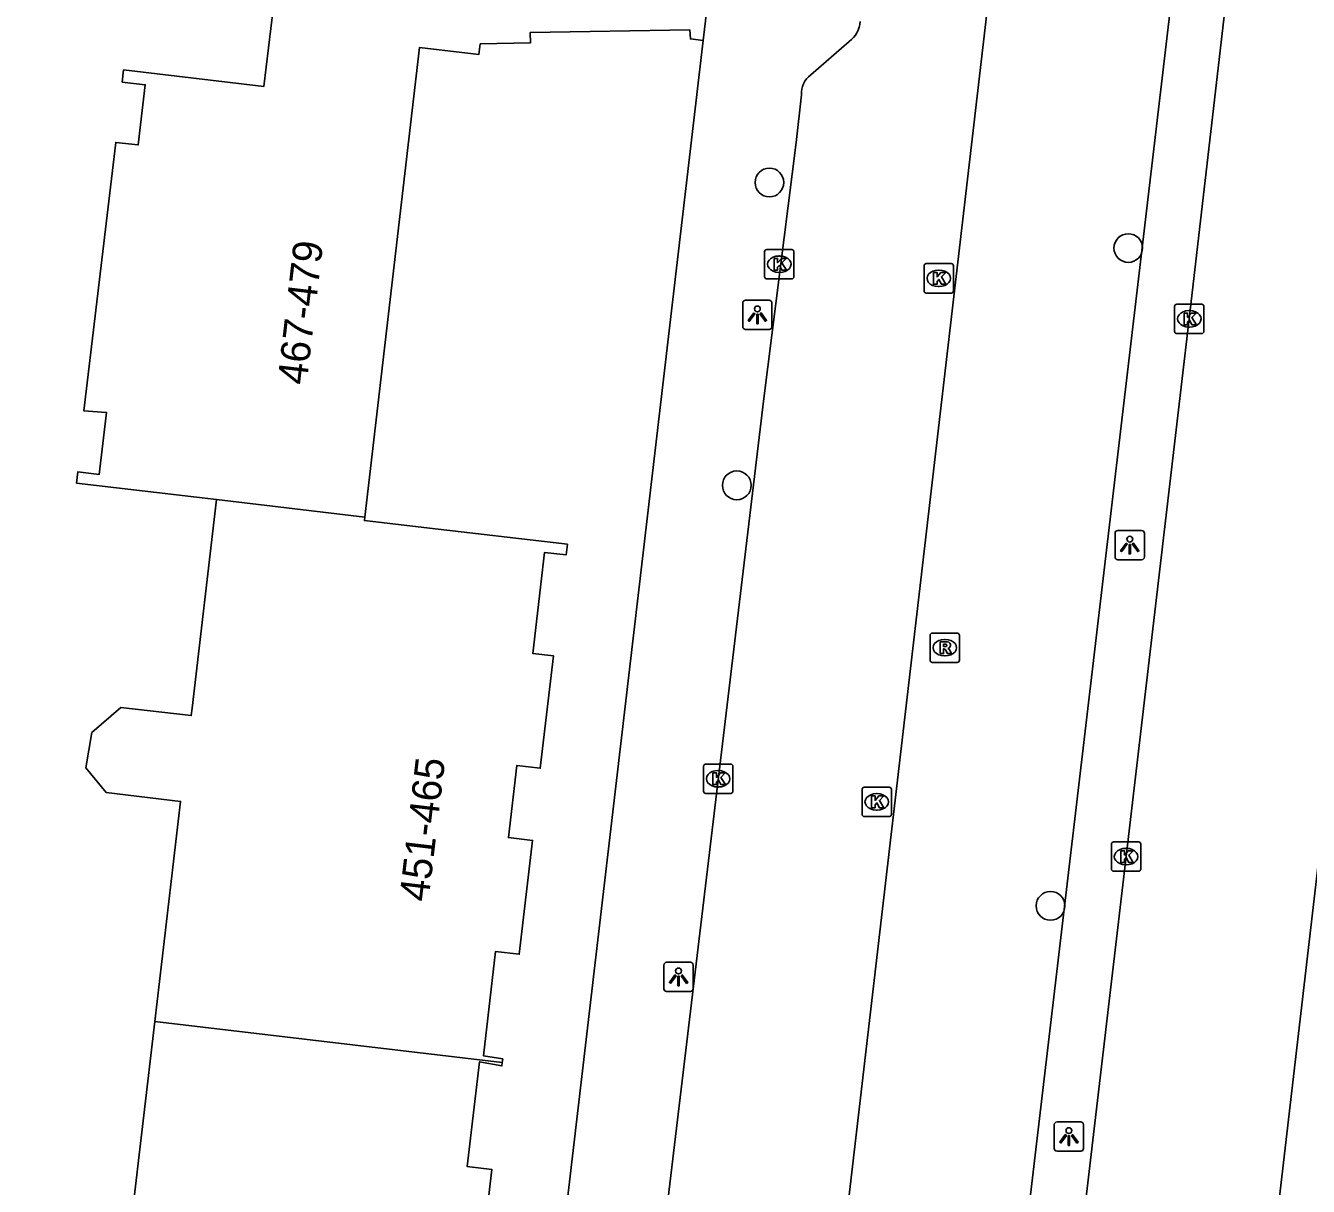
# Model space of a CAD drawing. Extents: x 160861 to 161308, y 384024 to 384878.
# Drawn here: x 161210.39 to 161254.09, y 384451.45 to 384490.99 of the extents above; entities that cross this region are included whole.
import ezdxf

# ---------------------------------------------------------------- set-up
doc = ezdxf.new("R2010")
doc.units = 0
for name, color, linetype in [('IMGEO_Boom', 7, 'Continuous'), ('IMGEO_Kolk', 7, 'Continuous'), ('IMGEO_Lichtpunt', 7, 'Continuous'), ('IMGEO_Pand', 7, 'Continuous'), ('IMGEO_Pand_nummerreeks', 7, 'Continuous'), ('IMGEO_Parkeervlak_open', 7, 'Continuous'), ('IMGEO_Rijbaan_lokaal_gesloten', 7, 'Continuous'), ('IMGEO_Rijbaan_lokaal_open', 7, 'Continuous'), ('IMGEO_Rioolput', 7, 'Continuous'), ('IMGEO_Voetpad_open', 7, 'Continuous')]:
    doc.layers.add(name, color=color, linetype=linetype)

msp = doc.modelspace()

# ---------------------------------------------------------------- linework, layer by layer
at = {"layer": 'IMGEO_Boom'}
for centre in [(161235.727, 384485.643), (161247.951, 384483.41), (161234.616, 384475.328), (161245.304, 384461.002)]:
    msp.add_circle(centre, 0.489, dxfattribs=at)
at = {"layer": 'IMGEO_Kolk'}
for p, q in [((161235.562, 384482.434), (161235.562, 384483.286)), ((161235.637, 384483.36), (161236.489, 384483.36)), ((161236.563, 384483.286), (161236.563, 384482.434)), ((161236.05, 384483.14), (161236.075, 384483.14)), ((161240.995, 384481.953), (161240.995, 384482.805)), ((161241.07, 384482.879), (161241.922, 384482.879)), ((161241.996, 384482.805), (161241.996, 384481.953)), ((161236.489, 384482.36), (161235.637, 384482.36)), ((161236.073, 384482.58), (161236.048, 384482.58)), ((161241.483, 384482.659), (161241.508, 384482.659)), ((161241.506, 384482.099), (161241.481, 384482.099)), ((161241.922, 384481.879), (161241.07, 384481.879)), ((161249.604, 384481.498), (161250.456, 384481.498)), ((161249.529, 384480.572), (161249.529, 384481.424)), ((161250.017, 384481.278), (161250.042, 384481.278)), ((161250.53, 384481.424), (161250.53, 384480.572)), ((161250.04, 384480.718), (161250.015, 384480.718)), ((161250.456, 384480.498), (161249.604, 384480.498)), ((161233.482, 384464.905), (161233.482, 384465.757)), ((161233.557, 384465.831), (161234.409, 384465.831)), ((161234.483, 384465.757), (161234.483, 384464.905)), ((161233.97, 384465.611), (161233.995, 384465.611)), ((161233.993, 384465.051), (161233.968, 384465.051)), ((161238.882, 384464.119), (161238.882, 384464.971)), ((161238.957, 384465.045), (161239.809, 384465.045)), ((161239.883, 384464.971), (161239.883, 384464.119)), ((161234.409, 384464.831), (161233.557, 384464.831)), ((161239.37, 384464.825), (161239.395, 384464.825)), ((161239.809, 384464.045), (161238.957, 384464.045)), ((161239.393, 384464.265), (161239.368, 384464.265)), ((161247.45, 384463.182), (161248.302, 384463.182)), ((161247.375, 384462.256), (161247.375, 384463.108)), ((161247.863, 384462.962), (161247.888, 384462.962)), ((161248.376, 384463.108), (161248.376, 384462.256)), ((161247.886, 384462.402), (161247.861, 384462.402)), ((161248.302, 384462.182), (161247.45, 384462.182))]:
    msp.add_line(p, q, dxfattribs=at)
for points in [[(161235.562, 384482.434), (161235.562, 384483.286)], [(161235.637, 384483.36), (161236.489, 384483.36)], [(161236.563, 384483.286), (161236.563, 384482.434)], [(161235.883, 384483.06), (161236.006, 384483.06), (161236.006, 384482.909), (161236.136, 384483.06), (161236.3, 384483.06), (161236.154, 384482.909), (161236.307, 384482.66), (161236.155, 384482.66), (161236.07, 384482.824), (161236.006, 384482.757), (161236.006, 384482.66), (161235.883, 384482.66), (161235.883, 384483.06)], [(161240.995, 384481.953), (161240.995, 384482.805)], [(161241.07, 384482.879), (161241.922, 384482.879)], [(161241.996, 384482.805), (161241.996, 384481.953)], [(161236.489, 384482.36), (161235.637, 384482.36)], [(161241.316, 384482.579), (161241.439, 384482.579), (161241.439, 384482.428), (161241.569, 384482.579), (161241.733, 384482.579), (161241.587, 384482.428), (161241.74, 384482.179), (161241.588, 384482.179), (161241.503, 384482.343), (161241.439, 384482.276), (161241.439, 384482.179), (161241.316, 384482.179), (161241.316, 384482.579)], [(161241.922, 384481.879), (161241.07, 384481.879)], [(161249.604, 384481.498), (161250.456, 384481.498)], [(161249.529, 384480.572), (161249.529, 384481.424)], [(161249.85, 384481.198), (161249.973, 384481.198), (161249.973, 384481.047), (161250.103, 384481.198), (161250.267, 384481.198), (161250.121, 384481.047), (161250.274, 384480.798), (161250.122, 384480.798), (161250.037, 384480.962), (161249.973, 384480.895), (161249.973, 384480.798), (161249.85, 384480.798), (161249.85, 384481.198)], [(161250.53, 384481.424), (161250.53, 384480.572)], [(161250.456, 384480.498), (161249.604, 384480.498)], [(161233.482, 384464.905), (161233.482, 384465.757)], [(161233.557, 384465.831), (161234.409, 384465.831)], [(161234.483, 384465.757), (161234.483, 384464.905)], [(161233.803, 384465.531), (161233.926, 384465.531), (161233.926, 384465.38), (161234.056, 384465.531), (161234.22, 384465.531), (161234.074, 384465.38), (161234.227, 384465.131), (161234.075, 384465.131), (161233.99, 384465.295), (161233.926, 384465.228), (161233.926, 384465.131), (161233.803, 384465.131), (161233.803, 384465.531)], [(161238.882, 384464.119), (161238.882, 384464.971)], [(161238.957, 384465.045), (161239.809, 384465.045)], [(161239.883, 384464.971), (161239.883, 384464.119)], [(161234.409, 384464.831), (161233.557, 384464.831)], [(161239.203, 384464.745), (161239.326, 384464.745), (161239.326, 384464.594), (161239.456, 384464.745), (161239.62, 384464.745), (161239.474, 384464.594), (161239.627, 384464.345), (161239.475, 384464.345), (161239.39, 384464.509), (161239.326, 384464.442), (161239.326, 384464.345), (161239.203, 384464.345), (161239.203, 384464.745)], [(161239.809, 384464.045), (161238.957, 384464.045)], [(161247.45, 384463.182), (161248.302, 384463.182)], [(161247.375, 384462.256), (161247.375, 384463.108)], [(161247.696, 384462.882), (161247.819, 384462.882), (161247.819, 384462.731), (161247.949, 384462.882), (161248.113, 384462.882), (161247.967, 384462.731), (161248.12, 384462.482), (161247.968, 384462.482), (161247.883, 384462.646), (161247.819, 384462.579), (161247.819, 384462.482), (161247.696, 384462.482), (161247.696, 384462.882)], [(161248.376, 384463.108), (161248.376, 384462.256)], [(161248.302, 384462.182), (161247.45, 384462.182)]]:
    msp.add_lwpolyline(points, dxfattribs=at)
for centre, start, end in [((161235.639, 384483.284), 91.552, 178.448), ((161235.639, 384483.284), 91.552, 178.448), ((161236.487, 384483.284), 1.552, 88.448), ((161236.487, 384483.284), 1.552, 88.448), ((161241.072, 384482.803), 91.552, 178.448), ((161241.072, 384482.803), 91.552, 178.448), ((161241.92, 384482.803), 1.552, 88.448), ((161241.92, 384482.803), 1.552, 88.448), ((161235.639, 384482.436), 181.552, 268.448), ((161235.639, 384482.436), 181.552, 268.448), ((161236.487, 384482.436), 271.552, 358.448), ((161236.487, 384482.436), 271.552, 358.448), ((161241.072, 384481.955), 181.552, 268.448), ((161241.072, 384481.955), 181.552, 268.448), ((161241.92, 384481.955), 271.552, 358.448), ((161241.92, 384481.955), 271.552, 358.448), ((161249.606, 384481.422), 91.552, 178.448), ((161249.606, 384481.422), 91.552, 178.448), ((161250.454, 384481.422), 1.552, 88.448), ((161250.454, 384481.422), 1.552, 88.448), ((161249.606, 384480.574), 181.552, 268.448), ((161249.606, 384480.574), 181.552, 268.448), ((161250.454, 384480.574), 271.552, 358.448), ((161250.454, 384480.574), 271.552, 358.448), ((161233.559, 384465.755), 91.552, 178.448), ((161233.559, 384465.755), 91.552, 178.448), ((161234.407, 384465.755), 1.552, 88.448), ((161234.407, 384465.755), 1.552, 88.448), ((161233.559, 384464.907), 181.552, 268.448), ((161233.559, 384464.907), 181.552, 268.448), ((161234.407, 384464.907), 271.552, 358.448), ((161234.407, 384464.907), 271.552, 358.448), ((161238.959, 384464.969), 91.552, 178.448), ((161238.959, 384464.969), 91.552, 178.448), ((161239.807, 384464.969), 1.552, 88.448), ((161239.807, 384464.969), 1.552, 88.448), ((161238.959, 384464.121), 181.552, 268.448), ((161238.959, 384464.121), 181.552, 268.448), ((161239.807, 384464.121), 271.552, 358.448), ((161239.807, 384464.121), 271.552, 358.448), ((161247.452, 384463.106), 91.552, 178.448), ((161247.452, 384463.106), 91.552, 178.448), ((161248.3, 384463.106), 1.552, 88.448), ((161248.3, 384463.106), 1.552, 88.448), ((161247.452, 384462.258), 181.552, 268.448), ((161247.452, 384462.258), 181.552, 268.448), ((161248.3, 384462.258), 271.552, 358.448), ((161248.3, 384462.258), 271.552, 358.448)]:
    msp.add_arc(centre, 0.0765, start, end, dxfattribs=at)
for centre, major_axis, ratio, start_param, end_param in [((161236.049, 384482.86), (-0.387, 0.002), 0.722429, 4.712389, 7.853982), ((161236.074, 384482.86), (-0.39, 0.002), 0.717154, 1.570796, 4.712389), ((161241.482, 384482.379), (-0.387, 0.002), 0.722429, 4.712389, 7.853982), ((161241.507, 384482.379), (-0.39, 0.002), 0.717154, 1.570796, 4.712389), ((161250.016, 384480.998), (-0.387, 0.002), 0.722429, 4.712389, 7.853982), ((161250.041, 384480.998), (-0.39, 0.002), 0.717154, 1.570796, 4.712389), ((161233.969, 384465.331), (-0.387, 0.002), 0.722429, 4.712389, 7.853982), ((161233.994, 384465.331), (-0.39, 0.002), 0.717154, 1.570796, 4.712389), ((161239.369, 384464.545), (-0.387, 0.002), 0.722429, 4.712389, 7.853982), ((161239.394, 384464.545), (-0.39, 0.002), 0.717154, 1.570796, 4.712389), ((161247.862, 384462.682), (-0.387, 0.002), 0.722429, 4.712389, 7.853982), ((161247.887, 384462.682), (-0.39, 0.002), 0.717154, 1.570796, 4.712389)]:
    msp.add_ellipse(centre, major_axis=major_axis, ratio=ratio, start_param=start_param, end_param=end_param, dxfattribs=at)
at = {"layer": 'IMGEO_Lichtpunt'}
for p, q in [((161234.817, 384481.539), (161234.817, 384480.732)), ((161234.817, 384481.539), (161234.817, 384480.732)), ((161235.719, 384481.634), (161234.911, 384481.634)), ((161235.719, 384481.634), (161234.911, 384481.634)), ((161235.813, 384480.732), (161235.813, 384481.539)), ((161235.813, 384480.732), (161235.813, 384481.539)), ((161234.911, 384480.638), (161235.719, 384480.638)), ((161234.911, 384480.638), (161235.719, 384480.638)), ((161247.503, 384473.695), (161247.503, 384472.888)), ((161247.503, 384473.695), (161247.503, 384472.888)), ((161248.405, 384473.79), (161247.597, 384473.79)), ((161248.405, 384473.79), (161247.597, 384473.79)), ((161248.499, 384472.888), (161248.499, 384473.695)), ((161248.499, 384472.888), (161248.499, 384473.695)), ((161247.597, 384472.794), (161248.405, 384472.794)), ((161247.597, 384472.794), (161248.405, 384472.794)), ((161232.132, 384458.987), (161232.132, 384458.18)), ((161232.132, 384458.987), (161232.132, 384458.18)), ((161233.034, 384459.082), (161232.226, 384459.082)), ((161233.034, 384459.082), (161232.226, 384459.082)), ((161233.128, 384458.18), (161233.128, 384458.987)), ((161233.128, 384458.18), (161233.128, 384458.987)), ((161232.226, 384458.086), (161233.034, 384458.086)), ((161232.226, 384458.086), (161233.034, 384458.086)), ((161245.431, 384453.547), (161245.431, 384452.74)), ((161245.431, 384453.547), (161245.431, 384452.74)), ((161246.333, 384453.642), (161245.525, 384453.642)), ((161246.333, 384453.642), (161245.525, 384453.642)), ((161246.427, 384452.74), (161246.427, 384453.547)), ((161246.427, 384452.74), (161246.427, 384453.547)), ((161245.525, 384452.646), (161246.333, 384452.646)), ((161245.525, 384452.646), (161246.333, 384452.646))]:
    msp.add_line(p, q, dxfattribs=at)
for points in [[(161235.191, 384481.203), (161235.23, 384481.175), (161235.042, 384480.913), (161235.004, 384480.94), (161235.191, 384481.203)], [(161235.293, 384481.155), (161235.34, 384481.155), (161235.34, 384480.833), (161235.293, 384480.833), (161235.293, 384481.155)], [(161235.403, 384481.175), (161235.441, 384481.202), (161235.628, 384480.94), (161235.589, 384480.912), (161235.403, 384481.175)], [(161247.877, 384473.359), (161247.916, 384473.331), (161247.728, 384473.069), (161247.69, 384473.096), (161247.877, 384473.359)], [(161247.979, 384473.311), (161248.026, 384473.311), (161248.026, 384472.989), (161247.979, 384472.989), (161247.979, 384473.311)], [(161248.089, 384473.331), (161248.127, 384473.358), (161248.314, 384473.096), (161248.275, 384473.068), (161248.089, 384473.331)], [(161232.506, 384458.651), (161232.545, 384458.623), (161232.357, 384458.361), (161232.319, 384458.388), (161232.506, 384458.651)], [(161232.608, 384458.603), (161232.655, 384458.603), (161232.655, 384458.281), (161232.608, 384458.281), (161232.608, 384458.603)], [(161232.718, 384458.623), (161232.756, 384458.65), (161232.943, 384458.388), (161232.904, 384458.36), (161232.718, 384458.623)], [(161245.805, 384453.211), (161245.844, 384453.183), (161245.656, 384452.921), (161245.618, 384452.948), (161245.805, 384453.211)], [(161245.907, 384453.163), (161245.954, 384453.163), (161245.954, 384452.841), (161245.907, 384452.841), (161245.907, 384453.163)], [(161246.017, 384453.183), (161246.055, 384453.21), (161246.242, 384452.948), (161246.203, 384452.92), (161246.017, 384453.183)]]:
    msp.add_lwpolyline(points, dxfattribs=at)
for centre in [(161235.316, 384481.337), (161248.002, 384473.493), (161232.631, 384458.785), (161245.93, 384453.345)]:
    msp.add_circle(centre, 0.0994, dxfattribs=at)
for centre, start, end in [((161234.911, 384481.539), 90, 180), ((161234.911, 384481.539), 90, 180), ((161235.719, 384481.539), 0, 90), ((161235.719, 384481.539), 0, 90), ((161234.911, 384480.732), 180, 270), ((161234.911, 384480.732), 180, 270), ((161235.719, 384480.732), 270, 0), ((161235.719, 384480.732), 270, 360), ((161247.597, 384473.695), 90, 180), ((161247.597, 384473.695), 90, 180), ((161248.405, 384473.695), 0, 90), ((161248.405, 384473.695), 0, 90), ((161247.597, 384472.888), 180, 270), ((161247.597, 384472.888), 180, 270), ((161248.405, 384472.888), 270, 0), ((161248.405, 384472.888), 270, 360), ((161232.226, 384458.987), 90, 180), ((161232.226, 384458.987), 90, 180), ((161233.034, 384458.987), 0, 90), ((161233.034, 384458.987), 0, 90), ((161232.226, 384458.18), 180, 270), ((161232.226, 384458.18), 180, 270), ((161233.034, 384458.18), 270, 0), ((161233.034, 384458.18), 270, 360), ((161245.525, 384453.547), 90, 180), ((161245.525, 384453.547), 90, 180), ((161246.333, 384453.547), 0, 90), ((161246.333, 384453.547), 0, 90), ((161245.525, 384452.74), 180, 270), ((161245.525, 384452.74), 180, 270), ((161246.333, 384452.74), 270, 0), ((161246.333, 384452.74), 270, 360)]:
    msp.add_arc(centre, 0.0946, start, end, dxfattribs=at)
at = {"layer": 'IMGEO_Pand'}
for points in [[(161216.895, 384474.841), (161212.119, 384475.402), (161212.165, 384475.786), (161212.896, 384475.699), (161213.139, 384477.814), (161212.377, 384477.864), (161213.461, 384487.008), (161214.223, 384486.925), (161214.464, 384488.973), (161213.68, 384489.065), (161213.728, 384489.477), (161218.508, 384488.916), (161218.817, 384491.547), (161220.343, 384491.368), (161220.921, 384496.293)], [(161233.969, 384494.717), (161233.475, 384490.485)], [(161221.943, 384474.242), (161223.81, 384490.245), (161225.833, 384490.009), (161225.875, 384490.364), (161227.583, 384490.401), (161227.582, 384490.749), (161233.011, 384490.844), (161233.037, 384490.536), (161233.475, 384490.485)], [(161216.895, 384474.841), (161216.062, 384467.741), (161216.032, 384467.482), (161213.631, 384467.764), (161212.64, 384466.907), (161212.437, 384465.709), (161213.133, 384464.859), (161215.67, 384464.561), (161214.79, 384457.059)], [(161221.943, 384474.242), (161216.895, 384474.841)], [(161226.627, 384455.669), (161226.641, 384455.789), (161225.986, 384455.899), (161226.392, 384459.446), (161227.205, 384459.351), (161227.658, 384463.23), (161226.836, 384463.326), (161227.122, 384465.781), (161227.92, 384465.688), (161228.367, 384469.518), (161227.666, 384469.6), (161228.068, 384473.043), (161228.801, 384472.957), (161228.843, 384473.321), (161223.954, 384473.891), (161221.93, 384474.127), (161221.943, 384474.242)], [(161214.79, 384457.059), (161213.996, 384450.298), (161213.963, 384450.018), (161211.581, 384450.296), (161210.561, 384449.515), (161210.39, 384448.363), (161211.174, 384447.531), (161212.091, 384447.417), (161213.641, 384447.235), (161212.753, 384439.672)], [(161214.79, 384457.059), (161226.627, 384455.669)], [(161224.604, 384438.28), (161224.621, 384438.47), (161223.96, 384438.547), (161224.355, 384441.932), (161225.05, 384441.851), (161225.508, 384445.774), (161224.815, 384445.855), (161225.101, 384448.301), (161225.824, 384448.217), (161226.268, 384452.025), (161225.436, 384452.123), (161225.852, 384455.691), (161226.613, 384455.55), (161226.627, 384455.669)]]:
    msp.add_lwpolyline(points, dxfattribs=at)
at = {"layer": 'IMGEO_Parkeervlak_open'}
msp.add_lwpolyline([(161236.799, 384395.17), (161238.006, 384395.04), (161238.15, 384396.266), (161250.377, 384500), (161251.596, 384511.132), (161256.785, 384556.041), (161250.737, 384556.74)], dxfattribs=at)
at = {"layer": 'IMGEO_Rijbaan_lokaal_gesloten'}
for points in [[(161261.966, 384583.337), (161261.579, 384580.114), (161259.33, 384560.777), (161257.178, 384542.439), (161254.83, 384522.177), (161252.438, 384501.823), (161250.03, 384480.998), (161247.876, 384462.682), (161246.021, 384446.828), (161243.88, 384428.499), (161241.912, 384411.162), (161239.6, 384390.894), (161238.653, 384382.516), (161238.178, 384378.283), (161237.763, 384375.367), (161237.563, 384374.434), (161237.479, 384374.076), (161237.25, 384373.157), (161237.241, 384373.124)], [(161245.611, 384386.656), (161254.88, 384466.32), (161259.354, 384504.899), (161266.33, 384564.879), (161266.816, 384568.826), (161267.446, 384572.759), (161268.148, 384576.401), (161269.166, 384580.645)]]:
    msp.add_lwpolyline(points, dxfattribs=at)
at = {"layer": 'IMGEO_Rijbaan_lokaal_open'}
for points in [[(161250.737, 384556.74), (161231.686, 384393.141)], [(161237.137, 384489.306), (161238.445, 384490.445)], [(161224.63, 384384.341), (161225.155, 384389.562), (161231.826, 384447.259), (161235.532, 384478.284), (161236.635, 384487.009), (161236.821, 384488.628)]]:
    msp.add_lwpolyline(points, dxfattribs=at)
for centre, radius, start, end in [((161237.894, 384491.187), 0.924, 306.6202, 356.4292), ((161237.572, 384488.69), 0.754, 125.2679, 184.7539)]:
    msp.add_arc(centre, radius, start, end, dxfattribs=at)
at = {"layer": 'IMGEO_Rioolput'}
for p, q in [((161241.201, 384469.37), (161241.201, 384470.222)), ((161241.276, 384470.296), (161242.128, 384470.296)), ((161242.202, 384470.222), (161242.202, 384469.37)), ((161241.689, 384470.076), (161241.714, 384470.076)), ((161242.128, 384469.296), (161241.276, 384469.296)), ((161241.712, 384469.516), (161241.687, 384469.516))]:
    msp.add_line(p, q, dxfattribs=at)
for points in [[(161241.201, 384469.37), (161241.201, 384470.222)], [(161241.276, 384470.296), (161242.128, 384470.296)], [(161242.202, 384470.222), (161242.202, 384469.37)], [(161241.79, 384469.994), (161241.538, 384469.996), (161241.538, 384469.596)], [(161241.538, 384469.596), (161241.662, 384469.596), (161241.662, 384469.758), (161241.673, 384469.758)], [(161241.716, 384469.915), (161241.662, 384469.915), (161241.662, 384469.834)], [(161241.662, 384469.834), (161241.714, 384469.834)], [(161241.72, 384469.729), (161241.791, 384469.596), (161241.931, 384469.596), (161241.866, 384469.722)], [(161242.128, 384469.296), (161241.276, 384469.296)]]:
    msp.add_lwpolyline(points, dxfattribs=at)
for centre, radius, start, end in [((161241.278, 384470.22), 0.0765, 91.552, 178.448), ((161241.278, 384470.22), 0.0765, 91.552, 178.448), ((161242.126, 384470.22), 0.0765, 1.552, 88.448), ((161242.126, 384470.22), 0.0765, 1.552, 88.448), ((161241.672, 384469.705), 0.0533, 26.0293, 88.6989), ((161241.698, 384470.023), 0.19, 274.7715, 282.9687), ((161241.722, 384469.819), 0.0964, 77.0061, 93.1865), ((161241.736, 384469.876), 0.0378, 276.6634, 79.6772), ((161241.789, 384469.884), 0.109, 350.3612, 89.416), ((161241.787, 384469.884), 0.112, 277.5842, 350.9817), ((161241.771, 384469.669), 0.108, 29.5134, 73.7905), ((161241.278, 384469.372), 0.0765, 181.552, 268.448), ((161241.278, 384469.372), 0.0765, 181.552, 268.448), ((161242.126, 384469.372), 0.0765, 271.552, 358.448), ((161242.126, 384469.372), 0.0765, 271.552, 358.448)]:
    msp.add_arc(centre, radius, start, end, dxfattribs=at)
for centre, major_axis, ratio, start_param, end_param in [((161241.688, 384469.796), (-0.387, 0.002), 0.722429, 4.712389, 7.853982), ((161241.713, 384469.796), (-0.39, 0.002), 0.717154, 1.570796, 4.712389)]:
    msp.add_ellipse(centre, major_axis=major_axis, ratio=ratio, start_param=start_param, end_param=end_param, dxfattribs=at)
at = {"layer": 'IMGEO_Voetpad_open'}
msp.add_lwpolyline([(161233.475, 384490.485), (161220.779, 384382.081)], dxfattribs=at)

# ---------------------------------------------------------------- texts
at = {"layer": 'IMGEO_Pand_nummerreeks'}
for s, rotation, p in [('467-479', 83.3368, (161219.958, 384478.724)), ('451-465', 83.2622, (161224.108, 384461.119))]:
    msp.add_text(s, height=1, rotation=rotation, dxfattribs=at).set_placement(p)

doc.saveas('drawing.dxf')
